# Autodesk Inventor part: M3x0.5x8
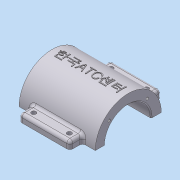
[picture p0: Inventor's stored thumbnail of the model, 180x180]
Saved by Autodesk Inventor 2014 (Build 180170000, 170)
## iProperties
Company: 한국ATC센터
Created: 2009-02
Part Number: M3x0.5x8
Document SubType Name: Modeling
Designer: KYOUNG IL JANG
Density: 2.71 g/cm^3
Mass: 199.244 g
Surface Area: 195.422 cm^2
Volume: 73.522 cm^3
Material: 알루미늄-6061
Vendor: CBT Solutions
Appearance: 알루미늄 - 평지
Author: KYOUNG IL JANG
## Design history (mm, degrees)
sketch "스케치1"
  geometry: L1 (-45, 40)-(45, 40); L2 (45, 40)-(45, -40); L3 (45, -40)-(-45, -40); L4 (-45, -40)-(-45, 40); 3 further points
  constraints: 8 end point, 2 midpoint, 2 parallel, 1 horizontal, 1 horizontal alignment, 1 perpendicular, 1 vertical alignment
  dimensions: "d0" = 90 distance of L2.end L3.end; "d1" = 80 distance of L1.end L2.end
extrude "돌출1" new body sketch "스케치1" distance "d2" = 10; taper "d3" = 0 deg
sketch "스케치2"
  geometry: L1 (40, 0)-(-40, 0) reference; C1 r 32.5 at (0, 80); 2 further points
  constraints: 1 centre point, 1 midpoint, 1 vertical alignment
  dimensions: "d4" = 65 diameter of C1; "d5" = 80 distance from line of C1.centre L1
extrude "돌출2" join sketch "스케치2" stored distance "d6" = 75; taper "d7" = 0 deg
sketch "스케치3"
  geometry: L1 (-7.5, -20)-(7.5, -20); L2 (7.5, 20)-(-7.5, 20); A1 r 20 centre (7.5, 0) between (7.5, -20) and (7.5, 20); A2 r 20 centre (-7.5, 0) between (-7.5, 20) and (-7.5, -20); 2 further points
  constraints: 4 end point, 4 point on circle, 4 tangent, 2 centre point, 1 horizontal, 1 horizontal alignment, 1 midpoint, 1 parallel, 1 vertical alignment
  dimensions: "d8" = 20 radius of A2; "d9" = 55 dimension on A1 A2
extrude "돌출3" join sketch "스케치3" stored distance "d10" = 75; taper "d11" = 0 deg
fillet "모깎기1" dims "d12" = 10
sketch "스케치4"
  geometry: L1 (-45, 0)-(-45, 10) reference; L2 (37.5, 47.5)-(-37.5, 47.5) reference; L3 (-45, 10)-(-27.513, 47.5); 1 further point
  constraints: 2 end point, 1 point on line
  dimensions: "d13" = 25 deg angle of L3 L1
sketch "스케치5"
  geometry: L1 (-40, 0)-(-40, 10) reference; L2 (-40, 10)-(-22.912, 56.95); 2 further points
  constraints: 2 end point, 2 other
  dimensions: "d14" = 20 deg angle of L2 L1
feature "리브1" dims "d15" = 1, "d16" = 6, "d17" = 0
feature "리브2" dims "d18" = 1, "d19" = 6, "d20" = 0
fillet "모깎기2" dims "d21" = 3
fillet "모깎기3" dims "d22" = 3
fillet "모깎기4" dims "d23" = 3
fillet "모깎기5" dims "d24" = 3
fillet "모깎기6" dims "d25" = 3
fillet "모깎기7" dims "d26" = 3
fillet "모깎기8" dims "d27" = 3
sketch "스케치6"
  geometry: A1 r 10 centre (35, -30) between (35, -40) and (45, -30) reference; 1 further point
hole "구멍1" sketch "스케치6" at (35, -30) diameter "d28" = 10; stored, may be unused: countersink angle "d32" = 90 deg, drill point angle "d34" = 118 deg; dims "d29" = 6, "d30" = 4, "d31" = 2, "d33" = 8
hole "구멍2" diameter "d37" = 45; stored, may be unused: countersink angle "d41" = 90 deg, drill point angle "d43" = 118 deg; dims "d35" = 10, "d36" = 10, "d38" = 6, "d39" = 4, "d40" = 2, "d42" = 8
sketch "스케치7"
  geometry: C1 r 22.5 at (0, 0) reference; 2 further points
  dimensions: "d44" = 135 deg dimension on C1.centre point (-18.738, 18.738) point (80, 0); "d45" = 26.5 distance of point (-18.738, 18.738) C1.centre
hole "구멍3" sketch "스케치7" at (-18.738, 18.738) diameter "d46" = 2.459; stored, may be unused: countersink angle "d50" = 90 deg, drill point angle "d52" = 118 deg; dims "d47" = 8, "d48" = 4, "d49" = 2, "d51" = 10
node "작업 평면1"
chamfer "모따기1" distance "d69" = 1; stored, may be unused: second distance "d70" = 2, angle "d71" = 45 deg
sketch "스케치9"
  geometry: L1 (-31.623, 87.5)-(-45, 87.5); L2 (-45, 87.5)-(-45, 72.5); L3 (-45, 72.5)-(-31.623, 72.5); A1 r 32.5 centre (0, 80) between (-31.623, 87.5) and (-31.623, 72.5) reference; 1 further point
  constraints: 6 end point, 2 parallel, 2 point on circle, 1 horizontal, 1 perpendicular
  dimensions: "d73" = 15 distance of L1.end L2.end; "d74" = 45 distance from line of A1.centre L2
extrude "돌출5" join sketch "스케치9" stored distance "d75" = 50; taper "d76" = 0 deg
fillet "모깎기10" dims "d77" = 3
fillet "모깎기11" dims "d78" = 3
sketch "스케치10"
  geometry: L1 (100.378, 66.389)-(0, 66.389); L2 (0, 66.389)-(0, -76.978); L3 (0, -76.978)-(100.378, -76.978); L4 (100.378, -76.978)-(100.378, 66.389); C1 r 32.5 at (0, 0) reference; 1 further point
  constraints: 8 end point, 2 parallel, 1 horizontal, 1 perpendicular, 1 point on line
extrude "돌출6" cut sketch "스케치10" stored distance "d79" = 10; taper "d80" = 0 deg
sketch "스케치11"
  geometry: C1 r 1.621 at (4.5, 4) reference; C2 r 1.621 at (39.5, 4) reference; 1 further point
hole "구멍5" sketch "스케치11" at (39.5, 4), (4.5, 4) diameter "d81" = 4.5; stored, may be unused: countersink angle "d85" = 90 deg, drill point angle "d87" = 118 deg; dims "d82" = 6, "d83" = 4, "d84" = 2, "d86" = 8
node "작업 평면2"
sketch "스케치12"
  geometry: 2 further points
  constraints: 1 coincident, 1 other
feature "엠보싱1" sketch "스케치12" dims "d8" = 20, "d9" = 55, "d88" = 0.5, "d89" = 0
node "솔리드1"
mirror "대칭1"
mirror "대칭2"
mirror "대칭3"
mirror "대칭4"
pattern_circular "원형 패턴1" dims angle "d54" = 360 deg
mirror "대칭5"
mirror "대칭6"
mirror "대칭7"
node "참조1"
node "참조2"
other parameters: "d56" = -117
